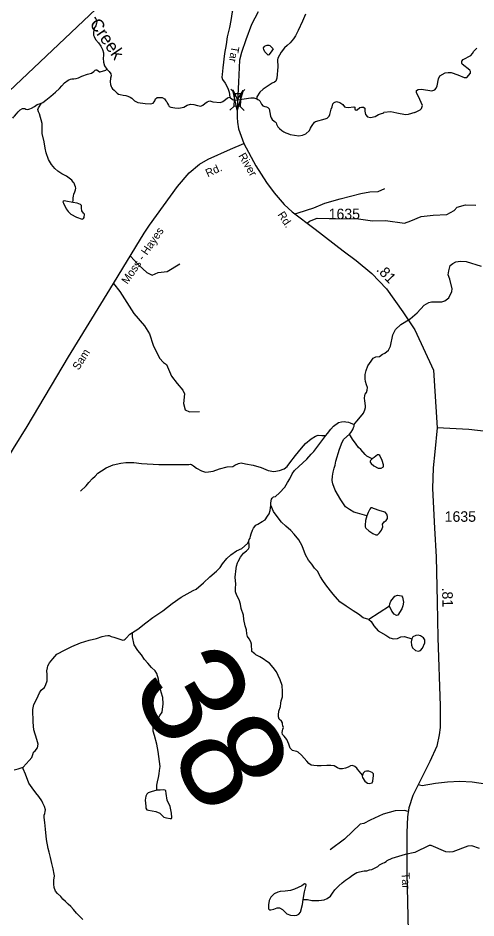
# Model space of a CAD drawing. Extents: x 2056842 to 2160602, y 826753 to 1016856.
# Drawn here: x 2106394 to 2111830, y 880850 to 891536 of the extents above; entities that cross this region are included whole.
import ezdxf

# ---------------------------------------------------------------- set-up
doc = ezdxf.new("R2010")
doc.units = 0
for name, color, linetype in [('Exist Hydrographic Creek Single Shore', 7, 'Continuous'), ('Exist Hydrographic Creek Single Shore Label', 7, 'Continuous'), ('Exist Hydrographic Misc Water Feature', 7, 'Continuous'), ('Exist Railroad Mainline', 7, 'Continuous'), ('Exist Road Non-System Type 51', 7, 'Continuous'), ('Exist Road Secondary Mileage Hundredths English Label', 7, 'Continuous'), ('Exist Road Secondary Structure Standard Bridge Attributed CELL', 7, 'Continuous'), ('Exist Road Secondary Structure Standard Bridge CELL', 7, 'Continuous'), ('Exist Road Secondary Structure Standard Bridge Number Label', 7, 'Continuous'), ('Exist Road Secondary Type 51 Attributed', 7, 'Continuous'), ('Exist Road Secondary Type 51 Label', 7, 'Continuous'), ('Exist Road Secondary Type 51 Number Label', 7, 'Continuous')]:
    doc.layers.add(name, color=color, linetype=linetype)

msp = doc.modelspace()

# ---------------------------------------------------------------- linework, layer by layer
at = {"layer": 'Exist Hydrographic Creek Single Shore'}
for points in [[(2108998, 892164), (2109000, 892077), (2108995, 891961), (2108981, 891812), (2108965, 891731), (2108954, 891674), (2108937, 891609), (2108919, 891505), (2108904, 891424), (2108877, 891311), (2108863, 891221), (2108843, 891113), (2108824, 890945), (2108819, 890866), (2108815, 890834), (2108821, 890807), (2108854, 890761), (2108885, 890703), (2108901, 890656), (2108907, 890597)], [(2109806, 891581), (2109772, 891498), (2109720, 891388), (2109686, 891323), (2109662, 891288), (2109623, 891241), (2109588, 891209), (2109557, 891182), (2109519, 891131), (2109477, 891060), (2109473, 891040), (2109477, 890955), (2109466, 890822), (2109453, 890784), (2109440, 890772), (2109412, 890764), (2109302, 890692), (2109264, 890657), (2109229, 890599), (2109227, 890576)], [(2107300, 891546), (2107318, 891526), (2107324, 891512), (2107328, 891502), (2107328, 891490), (2107324, 891476), (2107322, 891462), (2107316, 891442), (2107298, 891414), (2107295, 891390), (2107291, 891362), (2107291, 891334), (2107299, 891318), (2107315, 891282), (2107349, 891240), (2107377, 891200), (2107397, 891162), (2107409, 891124), (2107409, 891092), (2107406, 891060), (2107408, 891012), (2107422, 890966), (2107448, 890930)], [(2111102, 890412), (2111168, 890446), (2111184, 890460), (2111194, 890498), (2111164, 890570), (2111125, 890650), (2111125, 890674), (2111143, 890686), (2111183, 890692), (2111305, 890673), (2111343, 890683), (2111359, 890701), (2111369, 890729), (2111383, 890813), (2111401, 890849), (2111462, 890885), (2111498, 890889), (2111534, 890889), (2111616, 890862), (2111689, 890828), (2111721, 890828), (2111764, 890881), (2111766, 890902), (2111758, 890918), (2111664, 890988), (2111660, 891000), (2111662, 891024), (2111678, 891042), (2111767, 891090), (2111789, 891115), (2111805, 891144), (2111839, 891177)], [(2106671, 890524), (2106687, 890534), (2106723, 890560), (2106783, 890608), (2106839, 890657), (2106885, 890697), (2106913, 890729), (2106946, 890767), (2106988, 890797), (2107016, 890811), (2107032, 890815), (2107056, 890815), (2107084, 890819), (2107112, 890827), (2107152, 890844), (2107218, 890870), (2107266, 890882), (2107294, 890902), (2107310, 890918), (2107322, 890920), (2107326, 890920), (2107330, 890920), (2107346, 890910), (2107362, 890898), (2107370, 890898), (2107438, 890918), (2107448, 890930)], [(2107448, 890930), (2107462, 890914), (2107474, 890902), (2107494, 890873), (2107498, 890849), (2107492, 890821), (2107488, 890777), (2107492, 890745), (2107501, 890723), (2107508, 890707), (2107516, 890695), (2107535, 890679), (2107553, 890661), (2107569, 890645), (2107587, 890633), (2107607, 890629), (2107643, 890621), (2107675, 890617), (2107699, 890609), (2107725, 890597), (2107743, 890583), (2107759, 890567), (2107775, 890552), (2107815, 890533), (2107903, 890519), (2107972, 890515), (2108000, 890524), (2108011, 890540), (2108019, 890552), (2108027, 890576), (2108045, 890592), (2108057, 890592), (2108105, 890593), (2108131, 890577), (2108147, 890553), (2108159, 890541), (2108167, 890521), (2108179, 890499), (2108187, 890487), (2108207, 890479), (2108254, 890468), (2108303, 890465), (2108363, 890477), (2108403, 890502), (2108443, 890514), (2108479, 890510), (2108523, 890496), (2108563, 890488), (2108587, 890500), (2108612, 890520), (2108639, 890542), (2108659, 890550), (2108671, 890552), (2108707, 890542), (2108797, 890533), (2108826, 890545), (2108855, 890570), (2108879, 890589), (2108907, 890597)], [(2108907, 890597), (2108938, 890568), (2108958, 890561), (2109000, 890565), (2109157, 890586), (2109191, 890586), (2109227, 890576)], [(2106332, 890345), (2106342, 890357), (2106352, 890369), (2106376, 890397), (2106395, 890423), (2106420, 890445), (2106448, 890461), (2106456, 890461), (2106475, 890462), (2106488, 890454), (2106512, 890450), (2106536, 890456), (2106553, 890464), (2106589, 890484), (2106621, 890508), (2106671, 890524)], [(2109227, 890576), (2109239, 890568), (2109255, 890562), (2109263, 890552), (2109271, 890536), (2109283, 890512), (2109299, 890492), (2109323, 890484), (2109343, 890482), (2109359, 890472), (2109363, 890469), (2109375, 890457), (2109389, 890369), (2109397, 890351), (2109411, 890331), (2109434, 890311), (2109446, 890303), (2109458, 890291), (2109462, 890275), (2109478, 890243), (2109496, 890223), (2109524, 890199), (2109550, 890183), (2109574, 890171), (2109598, 890163), (2109626, 890153), (2109727, 890137), (2109770, 890146), (2109809, 890159), (2109852, 890202), (2109864, 890226), (2109877, 890246), (2109893, 890270), (2109906, 890286), (2109914, 890298), (2109925, 890308), (2110041, 890337), (2110065, 890345), (2110089, 890371), (2110095, 890391), (2110110, 890453), (2110122, 890481), (2110131, 890516), (2110148, 890532), (2110176, 890543), (2110212, 890533), (2110251, 890507), (2110271, 890483), (2110286, 890476), (2110312, 890474), (2110381, 890481), (2110390, 890476), (2110393, 890453), (2110406, 890442), (2110419, 890444), (2110452, 890472), (2110470, 890476), (2110494, 890476), (2110510, 890464), (2110511, 890428), (2110519, 890390), (2110544, 890362), (2110576, 890353), (2110633, 890366), (2110673, 890390), (2110707, 890402), (2110725, 890406), (2110737, 890412)], [(2111102, 890412), (2111025, 890389), (2110993, 890385), (2110891, 890405), (2110819, 890420), (2110737, 890412)], [(2111133, 888036), (2111213, 888128), (2111271, 888157), (2111301, 888165), (2111425, 888167), (2111460, 888176), (2111508, 888212), (2111542, 888290), (2111546, 888322), (2111519, 888434), (2111501, 888486), (2111507, 888534), (2111525, 888598), (2111555, 888622), (2111592, 888642), (2111644, 888648), (2111712, 888645), (2111893, 888589)], [(2110747, 887555), (2110793, 887593), (2110817, 887641), (2110844, 887773), (2110876, 887839), (2110936, 887895), (2111049, 887962), (2111133, 888036)], [(2110383, 886708), (2110396, 886726), (2110416, 886748), (2110460, 886800), (2110496, 886842), (2110512, 886883), (2110520, 886911), (2110520, 886931), (2110511, 886991), (2110508, 887023), (2110511, 887054), (2110515, 887070), (2110529, 887091), (2110537, 887115), (2110541, 887147), (2110529, 887179), (2110517, 887219), (2110513, 887251), (2110515, 887303), (2110526, 887350), (2110546, 887407), (2110586, 887463), (2110610, 887495), (2110642, 887512), (2110684, 887518), (2110721, 887546), (2110741, 887553), (2110747, 887555)], [(2110047, 886577), (2110067, 886603), (2110107, 886655), (2110137, 886691), (2110197, 886732), (2110232, 886742), (2110265, 886744), (2110284, 886742), (2110316, 886738), (2110336, 886728), (2110364, 886716), (2110383, 886708)], [(2107137, 885918), (2107201, 885980), (2107235, 886022), (2107277, 886067), (2107309, 886095), (2107343, 886131), (2107383, 886159), (2107439, 886193), (2107524, 886229), (2107614, 886252), (2107674, 886260), (2107770, 886260), (2107858, 886248), (2108066, 886235), (2108314, 886234), (2108330, 886234), (2108422, 886236), (2108442, 886238), (2108454, 886234), (2108478, 886218), (2108514, 886190), (2108570, 886159), (2108619, 886143), (2108655, 886149), (2108711, 886155), (2108786, 886181), (2108878, 886206), (2108942, 886212), (2108966, 886226), (2109010, 886248), (2109042, 886256), (2109094, 886244), (2109186, 886225), (2109278, 886199), (2109362, 886163), (2109430, 886151), (2109498, 886165), (2109551, 886184), (2109588, 886210), (2109622, 886254), (2109688, 886342), (2109758, 886430), (2109807, 886484), (2109875, 886541), (2109923, 886569), (2109955, 886581), (2109999, 886577), (2110047, 886577)], [(2109394, 885751), (2109394, 885775), (2109398, 885803), (2109401, 885823), (2109409, 885835), (2109425, 885851), (2109449, 885855), (2109497, 885897), (2109561, 885966), (2109593, 886020), (2109621, 886064), (2109646, 886124), (2109674, 886162), (2109728, 886210), (2109820, 886298), (2109872, 886357), (2109906, 886389), (2109987, 886501), (2110047, 886577)], [(2110534, 885624), (2110422, 885656), (2110378, 885668), (2110328, 885700), (2110282, 885732), (2110227, 885816), (2110157, 885928), (2110129, 886003), (2110123, 886044), (2110125, 886094), (2110135, 886142), (2110146, 886189), (2110158, 886228), (2110168, 886272), (2110209, 886416), (2110241, 886498), (2110263, 886534), (2110327, 886595)], [(2109133, 885324), (2109139, 885344), (2109151, 885360), (2109155, 885384), (2109163, 885413), (2109179, 885453), (2109188, 885477), (2109216, 885513), (2109240, 885525), (2109292, 885557), (2109328, 885579), (2109356, 885619), (2109376, 885649), (2109386, 885687), (2109394, 885751)], [(2107753, 884238), (2107818, 884278), (2107912, 884353), (2107996, 884417), (2108114, 884495), (2108225, 884582), (2108329, 884660), (2108403, 884700), (2108471, 884738), (2108507, 884755), (2108597, 884831), (2108670, 884901), (2108750, 884969), (2108794, 885013), (2108822, 885053), (2108871, 885118), (2108919, 885162), (2108989, 885210), (2109051, 885236), (2109117, 885296), (2109133, 885324)], [(2106456, 882642), (2106526, 882720), (2106557, 882757), (2106574, 882802), (2106579, 882820), (2106598, 882833), (2106626, 882871), (2106632, 882914), (2106616, 882970), (2106581, 883085), (2106575, 883176), (2106571, 883325), (2106582, 883383), (2106619, 883452), (2106647, 883523), (2106669, 883555), (2106693, 883573), (2106709, 883588), (2106724, 883621), (2106738, 883667), (2106740, 883741), (2106736, 883785), (2106744, 883821), (2106746, 883845), (2106762, 883873), (2106768, 883881), (2106788, 883905), (2106808, 883925), (2106856, 883984), (2106955, 884034), (2107031, 884072), (2107137, 884116), (2107237, 884147), (2107325, 884167), (2107393, 884191), (2107429, 884201), (2107461, 884205), (2107477, 884205), (2107501, 884194), (2107533, 884186), (2107601, 884162), (2107637, 884150), (2107653, 884154), (2107665, 884162), (2107677, 884174), (2107721, 884218), (2107753, 884238)], [(2108043, 882366), (2108040, 882427), (2108048, 882467), (2108060, 882519), (2108068, 882561), (2108072, 882601), (2108081, 882650), (2108057, 882825), (2108041, 882915), (2108012, 883015), (2107998, 883069), (2107998, 883109), (2108006, 883145), (2108022, 883177), (2108052, 883211), (2108078, 883253), (2108105, 883294), (2108117, 883394), (2108111, 883469), (2108095, 883533), (2108074, 883615), (2108060, 883687), (2108040, 883753), (2108022, 883785), (2107978, 883825), (2107934, 883875), (2107896, 883917), (2107859, 883973), (2107815, 884026), (2107773, 884094), (2107753, 884190), (2107753, 884238)], [(2106350, 882607), (2106396, 882620), (2106456, 882642)], [(2107163, 880833), (2107119, 880877), (2107087, 880909), (2107051, 880951), (2107019, 880986), (2106988, 881014), (2106956, 881046), (2106927, 881074), (2106902, 881104), (2106862, 881142), (2106838, 881168), (2106824, 881212), (2106820, 881250), (2106820, 881298), (2106828, 881352), (2106824, 881372), (2106813, 881432), (2106797, 881496), (2106781, 881568), (2106765, 881632), (2106753, 881676), (2106732, 881783), (2106722, 881905), (2106714, 881985), (2106704, 882041), (2106704, 882069), (2106711, 882089), (2106715, 882113), (2106719, 882133), (2106709, 882173), (2106689, 882213), (2106675, 882241), (2106643, 882293), (2106606, 882335), (2106563, 882395), (2106524, 882451), (2106484, 882559), (2106456, 882622), (2106456, 882642)], [(2111873, 881676), (2111779, 881708), (2111731, 881703), (2111555, 881635), (2111519, 881630), (2111471, 881636), (2111299, 881709), (2111275, 881710), (2111103, 881629), (2110991, 881602), (2110830, 881555), (2110770, 881527)], [(2109779, 881069), (2109830, 881069), (2109882, 881057), (2109914, 881058), (2109966, 881056), (2110026, 881064), (2110062, 881080), (2110102, 881108), (2110128, 881144), (2110156, 881186), (2110200, 881232), (2110243, 881269), (2110279, 881297), (2110329, 881329), (2110365, 881359), (2110397, 881379), (2110417, 881391), (2110449, 881399), (2110503, 881411), (2110535, 881411), (2110567, 881422), (2110595, 881426), (2110627, 881442), (2110663, 881462), (2110686, 881481), (2110726, 881499), (2110742, 881507), (2110762, 881521), (2110770, 881528)]]:
    msp.add_lwpolyline(points, dxfattribs=at)
at = {"layer": 'Exist Hydrographic Misc Water Feature'}
msp.add_line((2110805, 884553), (2110556, 884395), dxfattribs=at)
for points in [[(2109400, 891195), (2109424, 891171), (2109400, 891133), (2109370, 891099), (2109360, 891095), (2109358, 891099), (2109348, 891109), (2109324, 891133), (2109314, 891152), (2109312, 891159), (2109308, 891181), (2109316, 891195), (2109328, 891205), (2109352, 891213), (2109372, 891215), (2109384, 891211), (2109400, 891195)], [(2107044, 889347), (2107047, 889375), (2107047, 889399), (2107051, 889419), (2107057, 889445), (2107068, 889471), (2107076, 889496), (2107080, 889516), (2107076, 889532), (2107068, 889551), (2107060, 889573), (2107048, 889587), (2107032, 889611), (2107002, 889635), (2106970, 889659), (2106914, 889685), (2106866, 889717), (2106830, 889749), (2106793, 889797), (2106755, 889856), (2106729, 889934), (2106717, 889990), (2106703, 890066), (2106682, 890166), (2106679, 890284), (2106650, 890399), (2106639, 890420), (2106631, 890448), (2106636, 890471), (2106671, 890524)], [(2107044, 889347), (2106960, 889362), (2106940, 889363), (2106930, 889359), (2106927, 889354), (2106932, 889338), (2106965, 889269), (2106989, 889237), (2107019, 889207), (2107088, 889173), (2107156, 889148), (2107171, 889155), (2107180, 889168), (2107182, 889205), (2107171, 889218), (2107151, 889247), (2107149, 889279), (2107147, 889308), (2107134, 889323), (2107096, 889337), (2107044, 889347)], [(2110327, 886595), (2110347, 886620), (2110367, 886648), (2110377, 886672), (2110385, 886688), (2110383, 886708)], [(2110599, 886302), (2110535, 886335), (2110516, 886354), (2110463, 886412), (2110434, 886438), (2110407, 886474), (2110364, 886535), (2110327, 886595)], [(2110599, 886302), (2110576, 886280), (2110572, 886273), (2110572, 886262), (2110586, 886245), (2110619, 886220), (2110670, 886191), (2110705, 886191), (2110732, 886208), (2110732, 886231), (2110715, 886282), (2110687, 886342), (2110675, 886350), (2110659, 886349), (2110620, 886319), (2110599, 886302)], [(2110556, 884395), (2110490, 884413), (2110434, 884457), (2110373, 884498), (2110289, 884552), (2110213, 884604), (2110133, 884696), (2110101, 884734), (2110048, 884805), (2110010, 884857), (2109986, 884901), (2109950, 884969), (2109914, 885005), (2109880, 885051), (2109840, 885099), (2109807, 885163), (2109765, 885270), (2109727, 885338), (2109671, 885406), (2109634, 885450), (2109572, 885504), (2109520, 885550), (2109468, 885615), (2109426, 885675), (2109394, 885751)], [(2110534, 885624), (2110520, 885568), (2110516, 885514), (2110516, 885494), (2110522, 885479), (2110556, 885445), (2110606, 885414), (2110641, 885400), (2110660, 885401), (2110685, 885421), (2110709, 885453), (2110723, 885496), (2110722, 885525), (2110738, 885553), (2110762, 885570), (2110778, 885593), (2110781, 885615), (2110772, 885643), (2110750, 885667), (2110691, 885686), (2110613, 885711), (2110597, 885721), (2110582, 885720), (2110569, 885705), (2110548, 885665), (2110534, 885624)], [(2110482, 882546), (2110423, 882615), (2110415, 882627), (2110391, 882647), (2110363, 882661), (2110339, 882657), (2110311, 882642), (2110279, 882628), (2110247, 882622), (2110215, 882622), (2110187, 882634), (2110147, 882658), (2110107, 882662), (2110059, 882660), (2109991, 882656), (2109943, 882657), (2109907, 882659), (2109875, 882665), (2109847, 882685), (2109823, 882713), (2109759, 882783), (2109721, 882819), (2109705, 882827), (2109685, 882829), (2109653, 882840), (2109625, 882868), (2109608, 882914), (2109584, 882968), (2109554, 883008), (2109534, 883028), (2109530, 883052), (2109538, 883092), (2109544, 883112), (2109536, 883132), (2109532, 883156), (2109532, 883168), (2109520, 883188), (2109494, 883212), (2109485, 883238), (2109485, 883262), (2109489, 883304), (2109509, 883360), (2109513, 883400), (2109519, 883428), (2109535, 883476), (2109535, 883538), (2109528, 883610), (2109506, 883676), (2109482, 883730), (2109462, 883774), (2109423, 883822), (2109379, 883877), (2109347, 883897), (2109303, 883927), (2109263, 883949), (2109215, 883973), (2109203, 883985), (2109187, 883997), (2109171, 884013), (2109165, 884101), (2109157, 884129), (2109137, 884165), (2109117, 884191), (2109113, 884207), (2109108, 884225), (2109104, 884273), (2109092, 884320), (2109076, 884392), (2109070, 884444), (2109041, 884526), (2109033, 884576), (2109017, 884626), (2108991, 884678), (2108975, 884722), (2108975, 884766), (2108981, 884814), (2108970, 884898), (2108982, 884998), (2108986, 885026), (2109000, 885066), (2109008, 885082), (2109036, 885136), (2109071, 885180), (2109105, 885208), (2109131, 885233), (2109139, 885248), (2109137, 885276), (2109133, 885324)], [(2110805, 884553), (2110807, 884580), (2110818, 884611), (2110865, 884670), (2110899, 884682), (2110944, 884676), (2110957, 884661), (2110969, 884601), (2110963, 884555), (2110949, 884522), (2110903, 884447), (2110888, 884443), (2110859, 884458), (2110832, 884493), (2110805, 884553)], [(2110556, 884395), (2110584, 884369), (2110616, 884317), (2110668, 884261), (2110760, 884209), (2110806, 884177), (2110852, 884163), (2110900, 884170), (2110936, 884190), (2110980, 884192), (2111069, 884165)], [(2111069, 884165), (2111061, 884127), (2111065, 884090), (2111077, 884059), (2111111, 884027), (2111146, 884019), (2111171, 884027), (2111196, 884054), (2111221, 884117), (2111221, 884154), (2111208, 884177), (2111173, 884198), (2111142, 884206), (2111115, 884204), (2111082, 884187), (2111069, 884165)], [(2110482, 882546), (2110478, 882534), (2110483, 882517), (2110510, 882476), (2110541, 882449), (2110563, 882446), (2110596, 882456), (2110607, 882473), (2110613, 882541), (2110612, 882563), (2110597, 882578), (2110559, 882592), (2110530, 882595), (2110512, 882591), (2110491, 882569), (2110482, 882546)], [(2108043, 882366), (2107973, 882347), (2107938, 882336), (2107921, 882320), (2107910, 882298), (2107905, 882247), (2107910, 882179), (2107912, 882152), (2107924, 882135), (2107944, 882129), (2107986, 882124), (2108029, 882113), (2108077, 882093), (2108105, 882066), (2108126, 882045), (2108156, 882038), (2108200, 882030), (2108216, 882032), (2108220, 882043), (2108214, 882095), (2108198, 882175), (2108166, 882247), (2108152, 882326), (2108148, 882359), (2108139, 882367), (2108122, 882370), (2108081, 882369), (2108043, 882366)], [(2109779, 881069), (2109796, 881159), (2109813, 881240), (2109809, 881252), (2109796, 881254), (2109761, 881232), (2109677, 881192), (2109628, 881177), (2109565, 881167), (2109505, 881165), (2109476, 881158), (2109434, 881137), (2109396, 881097), (2109373, 881057), (2109367, 881007), (2109367, 880959), (2109377, 880948), (2109395, 880947), (2109429, 880956), (2109470, 880972), (2109497, 880970), (2109532, 880950), (2109586, 880899), (2109627, 880883), (2109671, 880880), (2109703, 880882), (2109728, 880896), (2109747, 880920), (2109769, 881009), (2109779, 881069)]]:
    msp.add_lwpolyline(points, dxfattribs=at)
at = {"layer": 'Exist Railroad Mainline'}
msp.add_lwpolyline([(2104782, 889189), (2104826, 889261), (2104880, 889350), (2104935, 889406), (2104983, 889458), (2105031, 889502), (2105083, 889550), (2105145, 889608), (2105203, 889661), (2105249, 889705), (2105312, 889767), (2105364, 889815), (2105412, 889855), (2105506, 889937), (2105695, 890108), (2107316, 891641)], dxfattribs=at)
at = {"layer": 'Exist Road Non-System Type 51'}
for points in [[(2109679, 889210), (2109718, 889224), (2109906, 889281), (2110037, 889338), (2110219, 889390), (2110464, 889454), (2110569, 889472), (2110668, 889477), (2110746, 889513)], [(2109826, 889100), (2109854, 889123), (2109945, 889159), (2110089, 889155), (2110437, 889153), (2110602, 889126), (2110756, 889130), (2110983, 889099), (2111057, 889127), (2111179, 889179), (2111320, 889196), (2111485, 889202), (2111572, 889251), (2111608, 889291), (2111707, 889316), (2111829, 889314)], [(2107726, 888712), (2107826, 888602), (2107921, 888516), (2107986, 888484), (2108058, 888516), (2108164, 888527), (2108316, 888615)], [(2107527, 888385), (2107602, 888288), (2107767, 888029), (2107897, 887882), (2107956, 887785), (2107998, 887652), (2108074, 887498), (2108120, 887446), (2108158, 887420), (2108216, 887282), (2108282, 887196), (2108349, 887117), (2108369, 887073), (2108360, 886957), (2108379, 886885), (2108430, 886858), (2108548, 886864)], [(2111026, 882116), (2110982, 882127), (2110869, 882122), (2110729, 882082), (2110573, 882013), (2110499, 881973), (2110455, 881964), (2110269, 881787), (2110100, 881658)]]:
    msp.add_lwpolyline(points, dxfattribs=at)
at = {"layer": 'Exist Road Secondary Structure Standard Bridge Attributed CELL'}
msp.add_lwpolyline([(2109068, 890676), (2108995, 890443), (2108942, 890681), (2109000, 890565)], close=True, dxfattribs=at)
at = {"layer": 'Exist Road Secondary Structure Standard Bridge CELL'}
for p, q in [((2108968, 890641), (2108921, 890692)), ((2109037, 890638), (2109087, 890685)), ((2108910, 890443), (2108961, 890490)), ((2109078, 890436), (2109032, 890487))]:
    msp.add_line(p, q, dxfattribs=at)
msp.add_lwpolyline([(2108961, 890490), (2108967, 890641), (2109038, 890638), (2109032, 890487)], close=True, dxfattribs=at)
at = {"layer": 'Exist Road Secondary Type 51 Attributed'}
for points in [[(2109246, 891609), (2109166, 891457), (2109096, 891275), (2109047, 891128), (2109024, 891034), (2109011, 890772), (2109003, 890620), (2109000, 890565)], [(2109000, 890565), (2108994, 890353), (2109000, 890299)], [(2109000, 890299), (2109012, 890221), (2109074, 890047)], [(2104122, 880831), (2104162, 881245), (2104275, 882231), (2104320, 882649), (2104343, 882749), (2104420, 882945), (2104578, 883259), (2104879, 883867), (2105010, 884125), (2105331, 884773), (2105502, 885050), (2105966, 885806), (2106340, 886425), (2106503, 886685), (2106994, 887513), (2107483, 888313), (2107891, 888983), (2107954, 889078), (2108287, 889534), (2108426, 889699), (2108548, 889800), (2108649, 889858), (2108915, 889980), (2109074, 890047)], [(2109074, 890047), (2109218, 889781), (2109344, 889581), (2109433, 889460), (2109551, 889323), (2109647, 889234), (2109922, 889027), (2110255, 888772), (2110408, 888655), (2110592, 888501), (2110767, 888319), (2110963, 888047), (2111102, 887833), (2111325, 887354), (2111369, 886668)], [(2111369, 886668), (2111340, 886386), (2111323, 886194), (2111314, 885951), (2111339, 885478), (2111356, 885138), (2111368, 884604), (2111378, 884176), (2111403, 883367), (2111406, 883112), (2111393, 883024), (2111365, 882889), (2111281, 882709), (2111142, 882429)], [(2117924, 885197), (2117683, 885218), (2117053, 885272), (2116800, 885304), (2116475, 885346), (2116204, 885419), (2115904, 885581), (2115692, 885762), (2115403, 886045), (2115157, 886250), (2114904, 886381), (2114617, 886451), (2114383, 886468), (2114097, 886443), (2113653, 886443), (2113268, 886455), (2112937, 886508), (2112193, 886599), (2111744, 886649), (2111369, 886668)], [(2111944, 882437), (2111786, 882462), (2111638, 882469), (2111491, 882464), (2111351, 882447), (2111191, 882418), (2111142, 882429)], [(2111142, 882429), (2111080, 882305), (2111032, 882156), (2111015, 882050), (2111007, 881864), (2111009, 881738), (2111010, 881386), (2111030, 880520), (2111040, 879728), (2111047, 878980), (2111053, 878458), (2111059, 878127)]]:
    msp.add_lwpolyline(points, dxfattribs=at)

# ---------------------------------------------------------------- texts
at = {"layer": 'Exist Hydrographic Creek Single Shore Label'}
msp.add_text('Creek', height=150, rotation=304.7303, dxfattribs=at).set_placement((2107237, 891467))
at = {"layer": 'Exist Road Secondary Mileage Hundredths English Label'}
for rotation, p in [(313.7618, (2110641, 888541)), (271.3266, (2111427, 884772))]:
    msp.add_text('.81', height=125, rotation=rotation, dxfattribs=at).set_placement(p)
at = {"layer": 'Exist Road Secondary Structure Standard Bridge Number Label'}
msp.add_text('38', height=1230.3, rotation=300, dxfattribs=at).set_placement((2107719, 883605))
at = {"layer": 'Exist Road Secondary Type 51 Label'}
for s, rotation, p in [('Tar', 260.4458, (2108928, 891206)), ('River', 299.989, (2109007, 889901)), ('Rd.', 24.1025, (2108645, 889645)), ('Rd.', 303.104, (2109471, 889201)), ('Moss - Hayes', 55.7752, (2107692, 888368)), ('Sam', 57.7603, (2107113, 887347)), ('Tar', 272.9922, (2110946, 881385))]:
    msp.add_text(s, height=95, rotation=rotation, dxfattribs=at).set_placement(p)
at = {"layer": 'Exist Road Secondary Type 51 Number Label'}
for p in [(2110081, 889147), (2111458, 885554)]:
    msp.add_text('1635', height=125, dxfattribs=at).set_placement(p)

doc.saveas('drawing.dxf')
